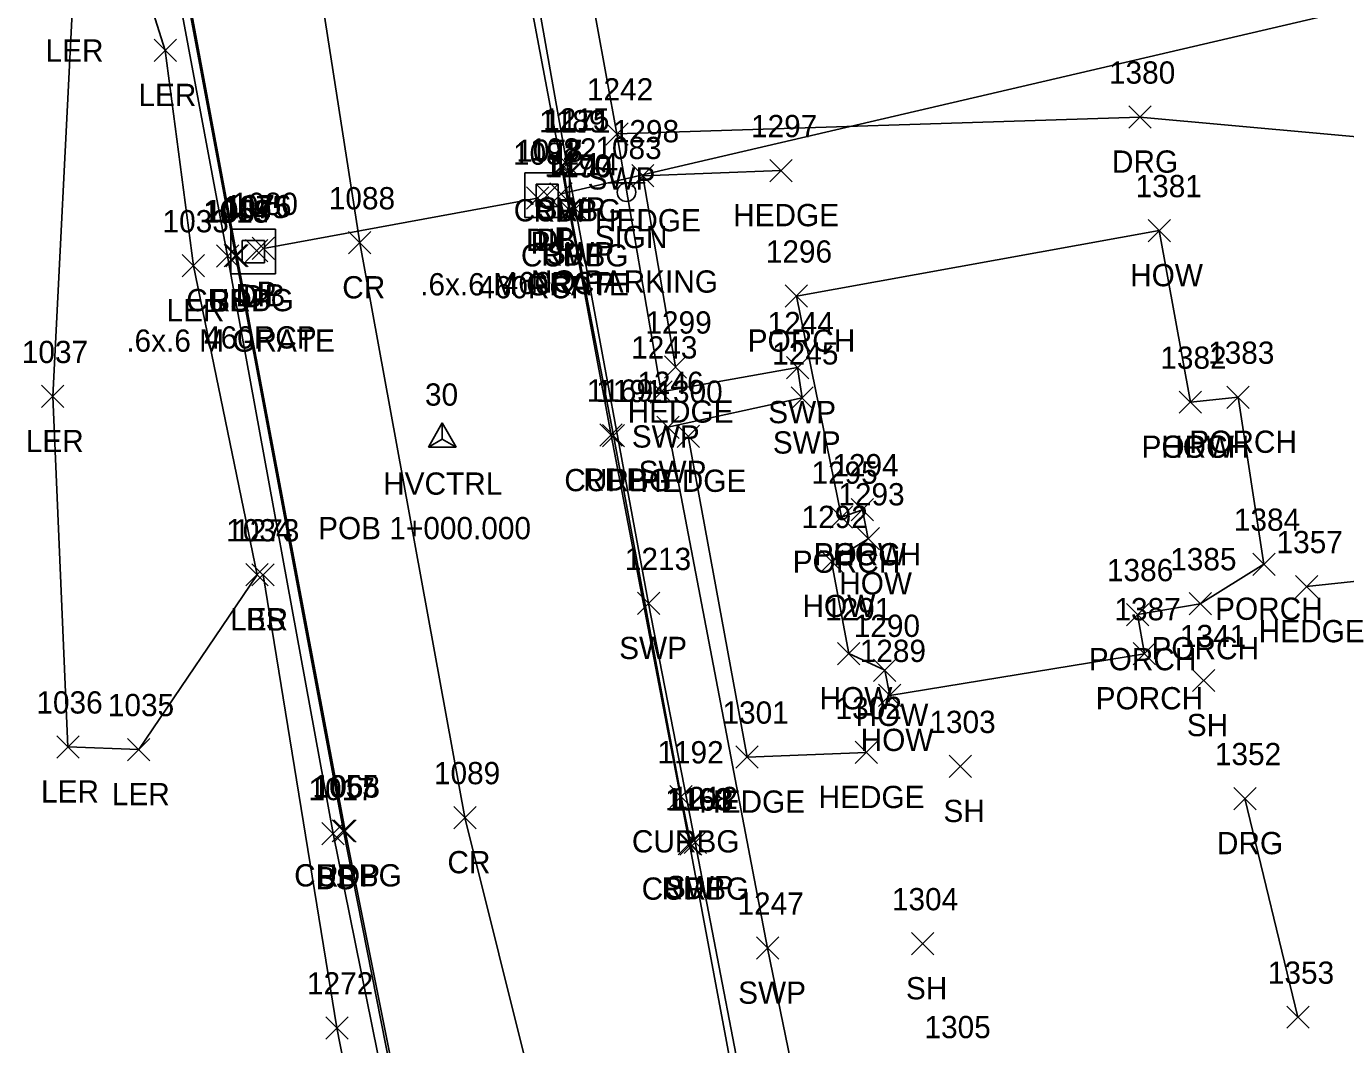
# Model space of a CAD drawing. Extents: x 462930 to 463548, y 29607 to 30453.
# Drawn here: x 463327.91 to 463364, y 30031.8 to 30059.67 of the extents above; entities that cross this region are included whole.
import ezdxf

# ---------------------------------------------------------------- set-up
doc = ezdxf.new("R2010")
doc.units = 0
for name, color, linetype in [('C_A', 7, 'Continuous'), ('C_C', 7, 'Continuous'), ('C_I', 7, 'Continuous'), ('CPSM', 7, 'Continuous'), ('D_A', 7, 'Continuous'), ('D_C', 7, 'Continuous'), ('D_I', 7, 'Continuous'), ('D_TIC', 7, 'Continuous'), ('DCP', 7, 'Continuous'), ('DS', 7, 'Continuous'), ('L_A', 7, 'Continuous'), ('L_I', 7, 'Continuous'), ('L_TIC', 7, 'Continuous'), ('LAHR', 7, 'Continuous'), ('LARO', 7, 'Continuous'), ('LBC', 7, 'Continuous'), ('LBF', 7, 'Continuous'), ('LELB', 7, 'Continuous'), ('P_A', 7, 'Continuous'), ('P_I', 7, 'Continuous'), ('P_TIC', 7, 'Continuous'), ('PET', 7, 'Continuous'), ('PRC', 7, 'Continuous'), ('R_A', 7, 'Continuous'), ('R_I', 7, 'Continuous'), ('R_TIC', 7, 'Continuous'), ('RC', 7, 'Continuous'), ('RDG', 7, 'Continuous'), ('RSW', 7, 'Continuous'), ('S_A', 7, 'Continuous'), ('S_C', 7, 'Continuous'), ('S_I', 7, 'Continuous'), ('SSGN', 7, 'Continuous')]:
    doc.layers.add(name, color=color, linetype=linetype)

msp = doc.modelspace()

# ---------------------------------------------------------------- linework, layer by layer
at = {"layer": 'CPSM'}
for p, q in [((463338.908, 30048.154), (463339.289, 30048.814)), ((463339.67, 30048.154), (463339.289, 30048.814)), ((463339.289, 30048.374), (463339.289, 30048.814)), ((463338.908, 30048.154), (463339.289, 30048.374)), ((463339.289, 30048.374), (463339.289, 30048.374)), ((463339.289, 30048.374), (463339.67, 30048.154)), ((463338.908, 30048.154), (463339.67, 30048.154))]:
    msp.add_line(p, q, dxfattribs=at)
at = {"layer": 'D_TIC'}
for points in [[(463341.591, 30054.665), (463342.201, 30055.275)], [(463342.201, 30054.665), (463341.591, 30055.275)], [(463341.854, 30054.745), (463342.464, 30055.355)], [(463342.464, 30054.745), (463341.854, 30055.355)], [(463342.234, 30054.779), (463342.844, 30055.389)], [(463342.844, 30054.779), (463342.234, 30055.389)], [(463333.908, 30053.226), (463334.518, 30053.836)], [(463334.518, 30053.226), (463333.908, 30053.836)], [(463334.092, 30053.29), (463334.702, 30053.9)], [(463334.702, 30053.29), (463334.092, 30053.9)]]:
    msp.add_lwpolyline(points, dxfattribs=at)
at = {"layer": 'DCP'}
for points in [[(463376.475, 30063.008), (463342.539, 30055.084)], [(463334.397, 30053.595), (463341.896, 30054.97)]]:
    msp.add_lwpolyline(points, dxfattribs=at)
at = {"layer": 'DS'}
for p, q in [((463341.549, 30055.659), (463342.768, 30055.659)), ((463341.549, 30054.44), (463341.549, 30055.659)), ((463342.768, 30055.659), (463342.768, 30054.44)), ((463341.854, 30054.745), (463341.854, 30055.354)), ((463341.854, 30055.354), (463342.463, 30055.354)), ((463342.16, 30055.05), (463342.16, 30055.05)), ((463342.16, 30055.05), (463342.16, 30055.05)), ((463342.463, 30055.354), (463342.463, 30054.745)), ((463342.463, 30054.745), (463341.854, 30054.745)), ((463342.768, 30054.44), (463341.549, 30054.44)), ((463333.508, 30054.116), (463334.727, 30054.116)), ((463333.508, 30052.897), (463333.508, 30054.116)), ((463334.727, 30054.116), (463334.727, 30052.897)), ((463333.813, 30053.202), (463333.813, 30053.811)), ((463333.813, 30053.811), (463334.422, 30053.811)), ((463334.422, 30053.811), (463334.422, 30053.202)), ((463334.119, 30053.507), (463334.119, 30053.507)), ((463334.119, 30053.507), (463334.119, 30053.507)), ((463334.727, 30052.897), (463333.508, 30052.897)), ((463334.422, 30053.202), (463333.813, 30053.202))]:
    msp.add_line(p, q, dxfattribs=at)
at = {"layer": 'L_TIC'}
for points in [[(463331.407, 30058.71), (463332.017, 30059.32)], [(463332.017, 30058.71), (463331.407, 30059.32)], [(463344.471, 30055.279), (463345.081, 30055.889)], [(463345.081, 30055.279), (463344.471, 30055.889)], [(463348.251, 30055.419), (463348.861, 30056.029)], [(463348.861, 30055.419), (463348.251, 30056.029)], [(463358.601, 30053.776), (463359.211, 30054.386)], [(463359.211, 30053.776), (463358.601, 30054.386)], [(463333.109, 30053.079), (463333.719, 30053.689)], [(463333.719, 30053.079), (463333.109, 30053.689)], [(463332.176, 30052.814), (463332.786, 30053.424)], [(463332.786, 30052.814), (463332.176, 30053.424)], [(463348.674, 30051.985), (463349.284, 30052.595)], [(463349.284, 30051.985), (463348.674, 30052.595)], [(463345.365, 30050.042), (463345.975, 30050.652)], [(463345.975, 30050.042), (463345.365, 30050.652)], [(463328.326, 30049.235), (463328.936, 30049.845)], [(463328.936, 30049.235), (463328.326, 30049.845)], [(463359.451, 30049.079), (463360.061, 30049.689)], [(463360.061, 30049.079), (463359.451, 30049.689)], [(463359.451, 30049.079), (463360.061, 30049.689)], [(463360.061, 30049.079), (463359.451, 30049.689)], [(463360.758, 30049.215), (463361.368, 30049.825)], [(463361.368, 30049.215), (463360.758, 30049.825)], [(463345.714, 30048.147), (463346.324, 30048.757)], [(463346.324, 30048.147), (463345.714, 30048.757)], [(463350.479, 30046.135), (463351.089, 30046.745)], [(463351.089, 30046.135), (463350.479, 30046.745)], [(463350.479, 30046.135), (463351.089, 30046.745)], [(463351.089, 30046.135), (463350.479, 30046.745)], [(463349.906, 30045.931), (463350.516, 30046.541)], [(463350.516, 30045.931), (463349.906, 30046.541)], [(463350.641, 30045.339), (463351.251, 30045.949)], [(463351.251, 30045.339), (463350.641, 30045.949)], [(463349.635, 30044.719), (463350.245, 30045.329)], [(463350.245, 30044.719), (463349.635, 30045.329)], [(463333.917, 30044.354), (463334.527, 30044.964)], [(463334.527, 30044.354), (463333.917, 30044.964)], [(463334.082, 30044.352), (463334.692, 30044.962)], [(463334.692, 30044.352), (463334.082, 30044.962)], [(463361.463, 30044.643), (463362.073, 30045.253)], [(463362.073, 30044.643), (463361.463, 30045.253)], [(463362.631, 30044.03), (463363.241, 30044.64)], [(463363.241, 30044.03), (463362.631, 30044.64)], [(463358.007, 30043.263), (463358.617, 30043.873)], [(463358.617, 30043.263), (463358.007, 30043.873)], [(463359.722, 30043.562), (463360.332, 30044.172)], [(463360.332, 30043.562), (463359.722, 30044.172)], [(463350.105, 30042.194), (463350.715, 30042.804)], [(463350.715, 30042.194), (463350.105, 30042.804)], [(463358.194, 30042.193), (463358.804, 30042.803)], [(463358.804, 30042.193), (463358.194, 30042.803)], [(463351.089, 30041.738), (463351.699, 30042.348)], [(463351.699, 30041.738), (463351.089, 30042.348)], [(463359.815, 30041.459), (463360.425, 30042.069)], [(463360.425, 30041.459), (463359.815, 30042.069)], [(463351.228, 30041.052), (463351.838, 30041.662)], [(463351.838, 30041.052), (463351.228, 30041.662)], [(463328.741, 30039.64), (463329.351, 30040.25)], [(463329.351, 30039.64), (463328.741, 30040.25)], [(463330.68, 30039.568), (463331.29, 30040.178)], [(463331.29, 30039.568), (463330.68, 30040.178)], [(463347.322, 30039.363), (463347.932, 30039.973)], [(463347.932, 30039.363), (463347.322, 30039.973)], [(463350.589, 30039.49), (463351.199, 30040.1)], [(463351.199, 30039.49), (463350.589, 30040.1)], [(463353.156, 30039.107), (463353.766, 30039.717)], [(463353.766, 30039.107), (463353.156, 30039.717)], [(463335.996, 30037.268), (463336.606, 30037.878)], [(463336.606, 30037.268), (463335.996, 30037.878)], [(463352.131, 30034.254), (463352.741, 30034.864)], [(463352.741, 30034.254), (463352.131, 30034.864)], [(463336.103, 30031.949), (463336.713, 30032.559)], [(463336.713, 30031.949), (463336.103, 30032.559)]]:
    msp.add_lwpolyline(points, dxfattribs=at)
at = {"layer": 'LAHR'}
for points in [[(463348.556, 30055.724), (463344.776, 30055.584), (463345.67, 30050.347)], [(463346.019, 30048.452), (463347.627, 30039.668), (463350.894, 30039.795)], [(463372.13, 30045.317), (463362.936, 30044.335)]]:
    msp.add_lwpolyline(points, dxfattribs=at)
at = {"layer": 'LARO'}
msp.add_lwpolyline([(463326.914, 30096.209), (463327.533, 30094.097), (463327.354, 30087.804), (463327.66, 30079.621), (463329.744, 30068.213), (463329.537, 30065.888), (463331.712, 30059.015), (463332.481, 30053.119), (463334.222, 30044.659), (463330.985, 30039.873), (463329.046, 30039.945), (463328.631, 30049.54), (463329.172, 30060.23), (463327.01, 30065.344)], dxfattribs=at)
at = {"layer": 'LBC'}
for points in [[(463358.906, 30054.081), (463348.979, 30052.29)], [(463358.906, 30054.081), (463359.756, 30049.384)], [(463351.533, 30041.357), (463351.394, 30042.043), (463350.41, 30042.499), (463349.94, 30045.024), (463350.946, 30045.644), (463350.784, 30046.44)]]:
    msp.add_lwpolyline(points, dxfattribs=at)
at = {"layer": 'LBF'}
for points in [[(463350.784, 30046.44), (463350.211, 30046.236), (463348.979, 30052.29)], [(463359.756, 30049.384), (463361.063, 30049.52), (463361.768, 30044.948), (463360.027, 30043.867), (463358.312, 30043.568), (463358.499, 30042.498)], [(463358.499, 30042.498), (463351.533, 30041.357)]]:
    msp.add_lwpolyline(points, dxfattribs=at)
at = {"layer": 'LELB'}
for points in [[(463338.373, 30022.22), (463340.767, 30011.24), (463345.965, 29995.767), (463346.937, 29987.36), (463347.521, 29987.525), (463346.646, 29996.093), (463342.063, 30011.435), (463339.344, 30022.565), (463336.301, 30037.573), (463333.414, 30053.384), (463330.633, 30068.275), (463328.629, 30079.728), (463328.086, 30089.487), (463328.627, 30097.184), (463330.299, 30105.361), (463329.682, 30105.522), (463327.994, 30097.289)], [(463336.408, 30032.254), (463334.387, 30044.657)], [(463336.408, 30032.254), (463338.373, 30022.22)]]:
    msp.add_lwpolyline(points, dxfattribs=at)
at = {"layer": 'P_TIC'}
for points in [[(463342.246, 30055.545), (463342.856, 30056.155)], [(463342.856, 30055.545), (463342.246, 30056.155)], [(463342.456, 30054.338), (463343.066, 30054.948)], [(463343.066, 30054.338), (463342.456, 30054.948)], [(463336.725, 30053.443), (463337.335, 30054.053)], [(463337.335, 30053.443), (463336.725, 30054.053)], [(463333.364, 30053.092), (463333.974, 30053.702)], [(463333.974, 30053.092), (463333.364, 30053.702)], [(463343.602, 30048.178), (463344.212, 30048.788)], [(463344.212, 30048.178), (463343.602, 30048.788)], [(463339.603, 30037.705), (463340.213, 30038.315)], [(463340.213, 30037.705), (463339.603, 30038.315)], [(463336.326, 30037.339), (463336.936, 30037.949)], [(463336.936, 30037.339), (463336.326, 30037.949)], [(463345.746, 30036.989), (463346.356, 30037.599)], [(463346.356, 30036.989), (463345.746, 30037.599)]]:
    msp.add_lwpolyline(points, dxfattribs=at)
at = {"layer": 'PET'}
for points in [[(463374.338, 29956.391), (463367.555, 29969.533), (463365.556, 29974.625), (463364.583, 29976.896), (463356.695, 29995.475), (463352.505, 30009.098), (463350.167, 30017.966), (463347.98, 30027.115), (463347.733, 30028.32), (463346.051, 30037.294), (463343.907, 30048.483), (463342.761, 30054.643), (463342.551, 30055.85), (463341.301, 30062.483), (463338.432, 30077.399), (463338.227, 30078.623), (463337.48, 30086.968), (463337.479, 30088.196), (463338.474, 30099.226), (463339.751, 30104.374), (463341.961, 30110.783)], [(463349.052, 29990.82), (463346.99, 29996.409), (463342.314, 30011.546), (463339.633, 30022.646), (463336.631, 30037.644), (463333.669, 30053.397), (463330.887, 30068.339), (463328.89, 30079.76), (463328.357, 30089.522), (463328.892, 30097.183), (463330.561, 30105.3)]]:
    msp.add_lwpolyline(points, dxfattribs=at)
at = {"layer": 'PRC'}
msp.add_lwpolyline([(463337.978, 30112.385), (463335.087, 30099.771), (463333.576, 30084.385), (463334.686, 30068.796), (463337.03, 30053.748), (463339.908, 30038.01), (463343.632, 30023.045), (463346.617, 30012.904), (463351.044, 29997.524), (463354.76, 29987.177), (463360.584, 29974.202), (463367.548, 29960.534), (463374.695, 29948.349)], dxfattribs=at)
at = {"layer": 'R_TIC'}
for points in [[(463358.072, 30056.885), (463358.682, 30057.495)], [(463358.682, 30056.885), (463358.072, 30057.495)], [(463343.763, 30056.424), (463344.373, 30057.034)], [(463344.373, 30056.424), (463343.763, 30057.034)], [(463342.285, 30055.551), (463342.895, 30056.161)], [(463342.895, 30055.551), (463342.285, 30056.161)], [(463342.392, 30055.601), (463343.002, 30056.211)], [(463343.002, 30055.601), (463342.392, 30056.211)], [(463342.482, 30054.318), (463343.092, 30054.928)], [(463343.092, 30054.318), (463342.482, 30054.928)], [(463342.629, 30054.375), (463343.239, 30054.985)], [(463343.239, 30054.375), (463342.629, 30054.985)], [(463333.324, 30053.092), (463333.934, 30053.702)], [(463333.934, 30053.092), (463333.324, 30053.702)], [(463348.706, 30050.026), (463349.316, 30050.636)], [(463349.316, 30050.026), (463348.706, 30050.636)], [(463344.973, 30049.359), (463345.583, 30049.969)], [(463345.583, 30049.359), (463344.973, 30049.969)], [(463348.831, 30049.195), (463349.441, 30049.805)], [(463349.441, 30049.195), (463348.831, 30049.805)], [(463345.159, 30048.39), (463345.769, 30049)], [(463345.769, 30048.39), (463345.159, 30049)], [(463343.669, 30048.165), (463344.279, 30048.775)], [(463344.279, 30048.165), (463343.669, 30048.775)], [(463344.628, 30043.569), (463345.238, 30044.179)], [(463345.238, 30043.569), (463344.628, 30044.179)], [(463345.518, 30038.276), (463346.128, 30038.886)], [(463346.128, 30038.276), (463345.518, 30038.886)], [(463360.944, 30038.227), (463361.554, 30038.837)], [(463361.554, 30038.227), (463360.944, 30038.837)], [(463336.278, 30037.344), (463336.888, 30037.954)], [(463336.888, 30037.344), (463336.278, 30037.954)], [(463345.785, 30036.981), (463346.395, 30037.591)], [(463346.395, 30036.981), (463345.785, 30037.591)], [(463345.905, 30037.025), (463346.515, 30037.635)], [(463346.515, 30037.025), (463345.905, 30037.635)], [(463347.883, 30034.133), (463348.493, 30034.743)], [(463348.493, 30034.133), (463347.883, 30034.743)], [(463362.393, 30032.242), (463363.003, 30032.852)], [(463363.003, 30032.242), (463362.393, 30032.852)]]:
    msp.add_lwpolyline(points, dxfattribs=at)
at = {"layer": 'RC'}
for points in [[(463330.433, 30105.335), (463330.506, 30105.311), (463328.851, 30097.179), (463328.319, 30089.513), (463328.85, 30079.744), (463330.845, 30068.328), (463333.629, 30053.397), (463336.583, 30037.649), (463339.548, 30022.613), (463342.224, 30011.501), (463346.871, 29996.398), (463346.791, 29996.353)], [(463342.59, 30055.856), (463342.787, 30054.623), (463343.974, 30048.47), (463345.823, 30038.581), (463346.09, 30037.286)]]:
    msp.add_lwpolyline(points, dxfattribs=at)
at = {"layer": 'RDG'}
for points in [[(463355.188, 30061.475), (463366.856, 30061.901), (463368.547, 30056.261), (463358.377, 30057.19)], [(463358.377, 30057.19), (463344.068, 30056.729)], [(463361.249, 30038.532), (463362.698, 30032.547)]]:
    msp.add_lwpolyline(points, dxfattribs=at)
at = {"layer": 'RSW'}
for points in [[(463374.235, 29956.952), (463367.745, 29969.631), (463365.689, 29974.684), (463364.801, 29976.975), (463360.584, 29986.798), (463357.266, 29995.548), (463352.711, 30009.142), (463350.357, 30017.977), (463347.93, 30028.371), (463346.21, 30037.33), (463344.933, 30043.874), (463342.934, 30054.68), (463342.697, 30055.906), (463341.529, 30062.506)], [(463343.219, 30061.394), (463344.068, 30056.729), (463345.278, 30049.664), (463349.011, 30050.331), (463349.136, 30049.5), (463345.464, 30048.695), (463348.188, 30034.438), (463349.394, 30028.571), (463351.516, 30018.874), (463354.847, 30019.881), (463355.152, 30018.851), (463351.945, 30017.653), (463354.43, 30009.022), (463358.466, 29996.654), (463360.056, 29991.977), (463362.488, 29992.816), (463362.797, 29991.975), (463360.41, 29991.038), (463367.128, 29975.306), (463368.967, 29969.775), (463370.499, 29966.766)]]:
    msp.add_lwpolyline(points, dxfattribs=at)
at = {"layer": 'SSGN'}
for p, q in [((463343.827, 30055.385), (463344.843, 30055.385)), ((463344.329, 30055.131), (463344.329, 30055.131))]:
    msp.add_line(p, q, dxfattribs=at)
msp.add_circle((463344.329, 30055.131), 0.254, dxfattribs=at)

# ---------------------------------------------------------------- texts
at = {"layer": 'C_A'}
msp.add_text('HVCTRL', height=0.6096, dxfattribs=at).set_placement((463337.671, 30046.85))
at = {"layer": 'C_C'}
msp.add_text('POB 1+000.000', height=0.6096, dxfattribs=at).set_placement((463335.893, 30045.631))
at = {"layer": 'C_I'}
msp.add_text('30', height=0.6096, dxfattribs=at).set_placement((463338.816, 30049.288))
at = {"layer": 'D_A'}
for s, height, p in [('DIB', 0.6096, (463341.581, 30053.526)), ('P', 0.61, (463341.706, 30053.446)), ('DI', 0.6096, (463341.872, 30053.526)), ('P', 0.61, (463342.349, 30053.56)), ('DIB', 0.6096, (463333.635, 30052.007)), ('DI', 0.6096, (463333.831, 30051.983)), ('P', 0.61, (463334.207, 30052.071))]:
    msp.add_text(s, height=height, dxfattribs=at).set_placement(p)
at = {"layer": 'D_C'}
for s, p in [('.6x.6 M GRATE', (463338.685, 30052.307)), ('460RCP', (463340.914, 30052.341)), ('460RCP', (463340.271, 30052.227)), ('460RCP', (463332.772, 30050.852)), ('.6x.6 M GRATE', (463330.644, 30050.764))]:
    msp.add_text(s, height=0.6096, dxfattribs=at).set_placement(p)
at = {"layer": 'D_I'}
for s, p in [('1081', (463341.224, 30055.884)), ('1077', (463341.314, 30055.964)), ('1078', (463341.315, 30055.964)), ('1082', (463341.694, 30055.998)), ('1075', (463333.274, 30054.421)), ('1076', (463333.351, 30054.445)), ('1080', (463333.526, 30054.509))]:
    msp.add_text(s, height=0.6096, dxfattribs=at).set_placement(p)
at = {"layer": 'L_A'}
for s, p in [('LER', (463328.435, 30058.706)), ('LER', (463330.975, 30057.491)), ('HEDGE', (463343.466, 30054.06)), ('HEDGE', (463347.246, 30054.2)), ('HOW', (463358.109, 30052.557)), ('LER', (463331.744, 30051.595)), ('BS', (463332.939, 30051.86)), ('PORCH', (463347.645, 30050.766)), ('HEDGE', (463344.36, 30048.823)), ('LER', (463327.894, 30048.016)), ('PORCH', (463359.729, 30047.996)), ('PORCH', (463358.422, 30047.86)), ('HOW', (463358.959, 30047.86)), ('HEDGE', (463344.709, 30046.928)), ('PORCH', (463348.877, 30044.712)), ('PORCH', (463349.45, 30044.916)), ('HOW', (463349.987, 30044.916)), ('HOW', (463350.149, 30044.12)), ('HOW', (463349.143, 30043.5)), ('PORCH', (463360.434, 30043.424)), ('LER', (463333.485, 30043.135)), ('BS', (463333.912, 30043.133)), ('HEDGE', (463361.626, 30042.811)), ('PORCH', (463358.693, 30042.343)), ('PORCH', (463356.978, 30042.044)), ('HOW', (463349.613, 30040.975)), ('PORCH', (463357.165, 30040.974)), ('HOW', (463350.597, 30040.519)), ('SH', (463359.659, 30040.24)), ('HOW', (463350.736, 30039.833)), ('LER', (463328.309, 30038.421)), ('LER', (463330.248, 30038.349)), ('HEDGE', (463349.584, 30038.271)), ('HEDGE', (463346.317, 30038.144)), ('SH', (463353, 30037.888)), ('BS', (463335.826, 30036.049)), ('SH', (463351.975, 30033.035))]:
    msp.add_text(s, height=0.6096, dxfattribs=at).set_placement(p)
at = {"layer": 'L_I'}
for s, p in [('1297', (463347.735, 30056.638)), ('1298', (463343.955, 30056.498)), ('1381', (463358.258, 30054.995)), ('1018', (463332.742, 30054.298)), ('1033', (463331.636, 30054.033)), ('1296', (463348.141, 30053.204)), ('1299', (463344.847, 30051.261)), ('1037', (463327.786, 30050.454)), ('1382', (463358.935, 30050.298)), ('1382', (463358.935, 30050.298)), ('1383', (463360.242, 30050.434)), ('1300', (463345.148, 30049.366)), ('1294', (463349.963, 30047.354)), ('1294', (463349.963, 30047.354)), ('1295', (463349.39, 30047.15)), ('1293', (463350.125, 30046.558)), ('1292', (463349.119, 30045.938)), ('1384', (463360.947, 30045.862)), ('1034', (463333.377, 30045.573)), ('1273', (463333.566, 30045.571)), ('1357', (463362.115, 30045.249)), ('1385', (463359.206, 30044.781)), ('1386', (463357.474, 30044.482)), ('1291', (463349.762, 30043.413)), ('1387', (463357.678, 30043.412)), ('1290', (463350.547, 30042.957)), ('1341', (463359.472, 30042.678)), ('1289', (463350.71, 30042.271)), ('1036', (463328.184, 30040.859)), ('1035', (463330.14, 30040.787)), ('1302', (463350.049, 30040.709)), ('1301', (463346.955, 30040.582)), ('1303', (463352.616, 30040.326)), ('1017', (463335.629, 30038.487)), ('1304', (463351.591, 30035.473)), ('1272', (463335.587, 30033.168)), ('1305', (463352.482, 30031.972))]:
    msp.add_text(s, height=0.6096, dxfattribs=at).set_placement(p)
at = {"layer": 'P_A'}
for s, p in [('RDP', (463341.785, 30054.326)), ('RDP', (463341.995, 30053.119)), ('CR', (463336.552, 30052.224)), ('RDP', (463332.903, 30051.873)), ('RDP', (463343.141, 30046.959)), ('CR', (463339.43, 30036.486)), ('RDP', (463335.865, 30036.12)), ('RDP', (463345.285, 30035.77))]:
    msp.add_text(s, height=0.6096, dxfattribs=at).set_placement(p)
at = {"layer": 'P_I'}
for s, p in [('1171', (463342.076, 30056.764)), ('1170', (463342.087, 30055.557)), ('1088', (463336.185, 30054.662)), ('1069', (463332.807, 30054.311)), ('1169', (463343.242, 30049.397)), ('1089', (463339.061, 30038.924)), ('1068', (463335.772, 30038.558)), ('1168', (463345.389, 30038.208))]:
    msp.add_text(s, height=0.6096, dxfattribs=at).set_placement(p)
at = {"layer": 'R_A'}
for s, p in [('DRG', (463357.611, 30055.666)), ('SWP', (463343.264, 30055.205)), ('CURBG', (463341.244, 30054.332)), ('SWP', (463341.893, 30054.382)), ('CURBG', (463341.441, 30053.099)), ('SWP', (463342.13, 30053.156)), ('CURBG', (463332.283, 30051.873)), ('SWP', (463348.207, 30048.807)), ('SWP', (463344.474, 30048.14)), ('SWP', (463348.332, 30047.976)), ('CURBG', (463342.628, 30046.946)), ('SWP', (463344.66, 30047.171)), ('SWP', (463344.129, 30042.35)), ('CURBG', (463344.477, 30037.057)), ('DRG', (463360.483, 30037.008)), ('CURBG', (463335.237, 30036.125)), ('CURBG', (463344.744, 30035.762)), ('SWP', (463345.406, 30035.806)), ('SWP', (463347.384, 30032.914))]:
    msp.add_text(s, height=0.6096, dxfattribs=at).set_placement(p)
at = {"layer": 'R_I'}
for s, p in [('1380', (463357.53, 30058.104)), ('1242', (463343.247, 30057.643)), ('1189', (463341.94, 30056.77)), ('1215', (463342.049, 30056.82)), ('1190', (463342.113, 30055.537)), ('1214', (463342.286, 30055.594)), ('1054', (463332.784, 30054.311)), ('1244', (463348.19, 30051.245)), ('1243', (463344.457, 30050.578)), ('1245', (463348.315, 30050.414)), ('1191', (463343.499, 30049.384)), ('1246', (463344.626, 30049.609)), ('1213', (463344.285, 30044.788)), ('1192', (463345.175, 30039.495)), ('1352', (463360.428, 30039.446)), ('1055', (463335.738, 30038.563)), ('1193', (463345.442, 30038.2)), ('1212', (463345.562, 30038.244)), ('1247', (463347.367, 30035.352)), ('1353', (463361.877, 30033.461))]:
    msp.add_text(s, height=0.6096, dxfattribs=at).set_placement(p)
at = {"layer": 'S_A'}
msp.add_text('SIGN', height=0.6096, dxfattribs=at).set_placement((463343.457, 30053.601))
at = {"layer": 'S_C'}
msp.add_text('NO PARKING', height=0.6096, dxfattribs=at).set_placement((463341.714, 30052.382))
at = {"layer": 'S_I'}
msp.add_text('1083', height=0.6096, dxfattribs=at).set_placement((463343.478, 30056.039))

doc.saveas('drawing.dxf')
